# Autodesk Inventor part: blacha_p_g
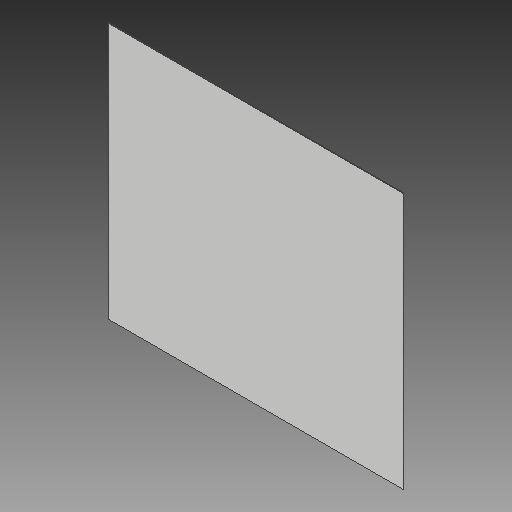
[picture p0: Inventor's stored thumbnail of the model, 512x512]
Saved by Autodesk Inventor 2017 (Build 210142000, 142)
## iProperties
Created: 2020-06
Part Number: blacha_p_g
Material: Generic
Document SubType Name: Modeling
Designer: WindowsX
Density: 1 g/cm^3
Appearance: Default
Mass: 3385.8 g
Surface Area: 22699.8 cm^2
Volume: 3385.8 cm^3
Author: WindowsX
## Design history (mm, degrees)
sketch "Szkic1"
  geometry: L1 (0, 0)-(1140, 0); L2 (1140, 0)-(1140, 990); L3 (1140, 990)-(0, 990); L4 (0, 990)-(0, 0)
  constraints: 8 end point, 2 parallel, 1 horizontal, 1 perpendicular
  dimensions: "d0" = 1140 distance of L2.end L3.end; "d1" = 990 distance of L1.start L3.end
extrude "Wyciągnięcie proste1" new body sketch "Szkic1" distance "d2" = 3; taper "d3" = 0 deg
node "Bryła1"
